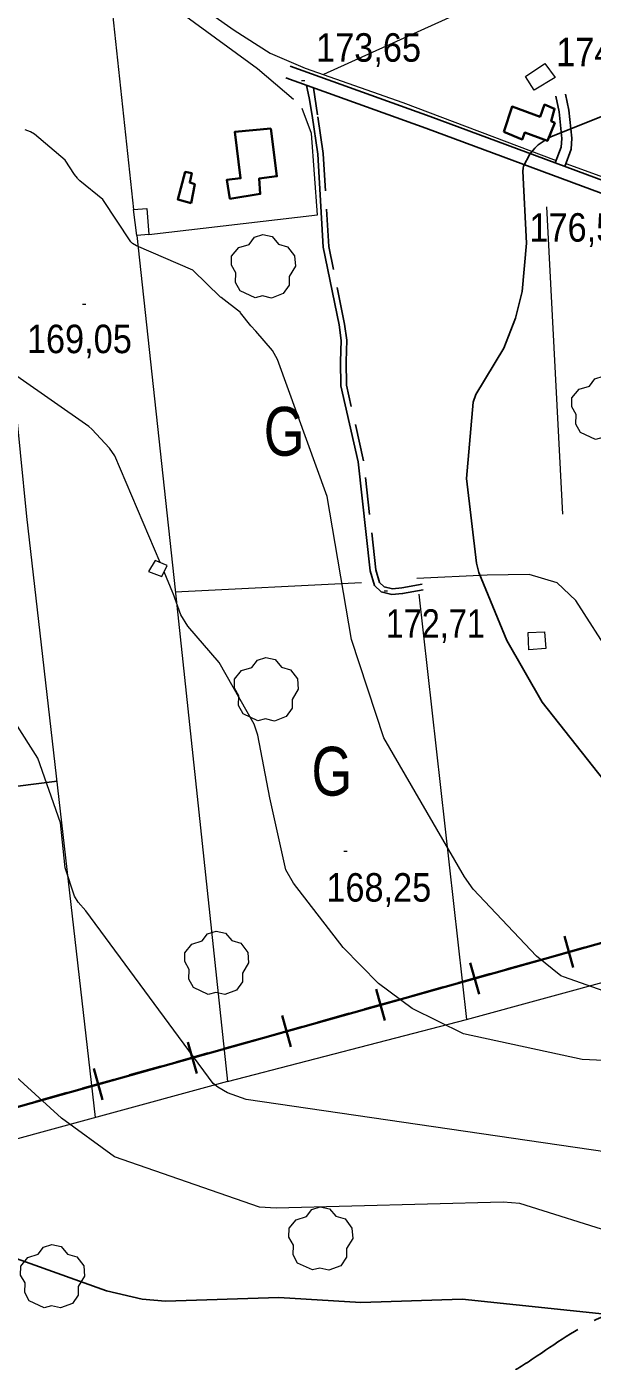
# Model space of a CAD drawing. Extents: x 480269 to 484877, y 4383588 to 4386804.
# Drawn here: x 481607.7 to 481781.2, y 4384664.9 to 4385074.9 of the extents above; entities that cross this region are included whole.
import ezdxf
from ezdxf.enums import TextEntityAlignment as Align

# ---------------------------------------------------------------- set-up
doc = ezdxf.new("R2010")
doc.units = 0
doc.header["$LTSCALE"] = 3.8
doc.linetypes.add('LONG_DASHED', pattern=[7.5, 6, -1.5])
doc.linetypes.add('MEDIUM_DASHED', pattern=[4.5, 3, -1.5])
for name, color, linetype, lineweight in [('25', 7, 'LONG_DASHED', 25), ('29', 7, 'Continuous', 13), ('34', 7, 'Continuous', 35), ('37', 7, 'Continuous', 25), ('38', 7, 'Continuous', 25), ('47', 7, 'Continuous', 35), ('51', 7, 'Continuous', 13), ('7', 7, 'Continuous', 13), ('8', 7, 'Continuous', 25), ('9', 7, 'Continuous', 13)]:
    doc.layers.add(name, color=color, linetype=linetype, lineweight=lineweight)
doc.layers.add('31', color=7, linetype='Continuous')

msp = doc.modelspace()

# ---------------------------------------------------------------- linework, layer by layer
at = {"layer": '25'}
msp.add_lwpolyline([(481616.96, 4384843.18), (481578.36, 4384838.22), (481534.2, 4384832.55)], dxfattribs=at)
at = {"layer": '29'}
for points in [[(481677.72, 4384991.61), (481673.18, 4384993.73), (481671.77, 4384996.27), (481671.87, 4384999.25), (481670.5, 4385001.66), (481670.54, 4385004.41), (481672.7, 4385007.01), (481675.89, 4385008.01), (481677.54, 4385010.2), (481680.11, 4385011.03), (481682.97, 4385010.38), (481684.92, 4385008.11), (481687.73, 4385007.29), (481689.86, 4385004.44), (481690.1, 4385001.31), (481688.22, 4384998.16), (481688.22, 4384995.48), (481686.4, 4384992.87), (481682.78, 4384991.53), (481680.01, 4384992.16)], [(481782.17, 4384948.1), (481777.63, 4384950.22), (481776.22, 4384952.76), (481776.32, 4384955.74), (481774.95, 4384958.15), (481774.99, 4384960.9), (481777.15, 4384963.5), (481780.34, 4384964.5), (481781.99, 4384966.69), (481784.56, 4384967.52), (481787.42, 4384966.87), (481789.37, 4384964.6), (481792.18, 4384963.78), (481794.31, 4384960.93), (481794.55, 4384957.8), (481792.67, 4384954.65), (481792.67, 4384951.97), (481790.85, 4384949.36), (481787.23, 4384948.02), (481784.46, 4384948.65)], [(481678.62, 4384861.69), (481674.08, 4384863.81), (481672.67, 4384866.35), (481672.77, 4384869.33), (481671.4, 4384871.74), (481671.44, 4384874.49), (481673.6, 4384877.09), (481676.79, 4384878.09), (481678.44, 4384880.28), (481681.01, 4384881.11), (481683.87, 4384880.46), (481685.82, 4384878.19), (481688.63, 4384877.37), (481690.76, 4384874.52), (481691, 4384871.39), (481689.12, 4384868.24), (481689.12, 4384865.56), (481687.3, 4384862.95), (481683.68, 4384861.61), (481680.91, 4384862.24)], [(481663.36, 4384777.65), (481658.82, 4384779.77), (481657.41, 4384782.31), (481657.51, 4384785.29), (481656.14, 4384787.7), (481656.18, 4384790.45), (481658.34, 4384793.05), (481661.53, 4384794.05), (481663.18, 4384796.24), (481665.75, 4384797.07), (481668.61, 4384796.42), (481670.56, 4384794.15), (481673.37, 4384793.33), (481675.5, 4384790.48), (481675.74, 4384787.35), (481673.86, 4384784.2), (481673.86, 4384781.52), (481672.04, 4384778.91), (481668.42, 4384777.57), (481665.65, 4384778.2)], [(481695.34, 4384693.01), (481690.8, 4384695.13), (481689.39, 4384697.67), (481689.49, 4384700.65), (481688.12, 4384703.06), (481688.16, 4384705.81), (481690.32, 4384708.41), (481693.51, 4384709.41), (481695.16, 4384711.6), (481697.73, 4384712.43), (481700.59, 4384711.78), (481702.54, 4384709.51), (481705.35, 4384708.69), (481707.48, 4384705.84), (481707.72, 4384702.71), (481705.84, 4384699.56), (481705.84, 4384696.88), (481704.02, 4384694.27), (481700.4, 4384692.93), (481697.63, 4384693.56)], [(481612.99, 4384681.4), (481608.45, 4384683.52), (481607.04, 4384686.06), (481607.14, 4384689.04), (481605.77, 4384691.45), (481605.81, 4384694.2), (481607.97, 4384696.8), (481611.16, 4384697.8), (481612.81, 4384699.99), (481615.38, 4384700.82), (481618.24, 4384700.17), (481620.19, 4384697.9), (481623, 4384697.08), (481625.13, 4384694.23), (481625.37, 4384691.1), (481623.49, 4384687.95), (481623.49, 4384685.27), (481621.67, 4384682.66), (481618.05, 4384681.32), (481615.28, 4384681.95)]]:
    msp.add_lwpolyline(points, close=True, dxfattribs=at)
at = {"layer": '34'}
for p, q in [((481772.65, 4384795.49), (481775.36, 4384785.86)), ((481778.82, 4384792.03), (481769.19, 4384789.32)), ((481743.77, 4384787.37), (481746.48, 4384777.74)), ((481764.38, 4384787.97), (481754.75, 4384785.26)), ((481749.94, 4384783.91), (481740.31, 4384781.2)), ((481714.89, 4384779.25), (481717.6, 4384769.62)), ((481735.5, 4384779.85), (481725.87, 4384777.14)), ((481721.06, 4384775.79), (481711.43, 4384773.08)), ((481686.01, 4384771.12), (481688.72, 4384761.5)), ((481706.62, 4384771.73), (481696.99, 4384769.02)), ((481692.18, 4384767.66), (481682.55, 4384764.96)), ((481657.13, 4384763), (481659.84, 4384753.38)), ((481677.74, 4384763.6), (481668.11, 4384760.9)), ((481663.3, 4384759.54), (481653.67, 4384756.84)), ((481628.25, 4384754.88), (481630.96, 4384745.26)), ((481648.86, 4384755.48), (481639.23, 4384752.78)), ((481634.42, 4384751.42), (481624.79, 4384748.72)), ((481619.98, 4384747.36), (481610.35, 4384744.65))]:
    msp.add_line(p, q, dxfattribs=at)
msp.add_lwpolyline([(482722, 4385145), (482428, 4385006), (482209, 4384913), (481448, 4384699), (481251, 4384637), (481013, 4384577), (480976, 4384524), (480944, 4384410), (480887.47, 4384143.52)], dxfattribs=at)
at = {"layer": '37'}
for points in [[(481688.48, 4385062.75), (481731.45, 4385047.27), (481811.75, 4385017.5), (481890.49, 4384988.72), (481976.99, 4384957.01), (482014.44, 4384943.22), (482020.77, 4384940.55), (482022.89, 4384939.41), (482024.83, 4384937.49), (482026.13, 4384935.48), (482026.91, 4384933.79), (482027.95, 4384931.72), (482028.6, 4384929.95), (482029.12, 4384927.71), (482038.5, 4384849.61)], [(481687.19, 4385059.17), (481730.14, 4385043.69), (481810.44, 4385013.93), (481889.18, 4384985.14), (481975.68, 4384953.43), (482012.99, 4384939.69), (482018.18, 4384937.72), (482020.39, 4384936.36), (482021.47, 4384935.48), (482022.48, 4384933.89), (482023.51, 4384931.99), (482024.83, 4384929.24), (482025.4, 4384926.81), (482034.72, 4384849.16)]]:
    msp.add_lwpolyline(points, dxfattribs=at)
at = {"layer": '38'}
for points in [[(481729.37, 4384901.9), (481723, 4384900.76), (481719.74, 4384900.5), (481716.46, 4384901.27), (481714.4, 4384903.27), (481713.1, 4384907.73), (481709.35, 4384941.26), (481704.04, 4384964.56), (481703.94, 4384972.03), (481704.14, 4384978.51), (481703.52, 4384983.25), (481698.63, 4385007.17), (481696.95, 4385035.74), (481695.22, 4385047.54), (481694.38, 4385052.97), (481693.55, 4385056.78)], [(481769.86, 4385033.03), (481771.72, 4385037.88), (481771.88, 4385040.56), (481771.02, 4385048.71), (481770.01, 4385053.51)]]:
    msp.add_lwpolyline(points, dxfattribs=at)
at = {"layer": '38', "linetype": 'MEDIUM_DASHED'}
for points in [[(481729.06, 4384903.6), (481722.78, 4384902.47), (481719.87, 4384902.24), (481717.32, 4384902.84), (481715.93, 4384904.19), (481714.8, 4384908.07), (481711.05, 4384941.55), (481705.77, 4384964.76), (481705.67, 4384972.01), (481705.87, 4384978.6), (481705.22, 4384983.54), (481700.34, 4385007.39), (481698.66, 4385035.92), (481696.93, 4385047.79), (481695.64, 4385056.12)], [(481772.75, 4385031.96), (481774.77, 4385037.22), (481774.97, 4385040.63), (481774.07, 4385049.19), (481773.02, 4385054.15)]]:
    msp.add_lwpolyline(points, dxfattribs=at)
at = {"layer": '38', "linetype": 'LONG_DASHED'}
msp.add_spline([(481521.41, 4384511.89), (481536.38, 4384525.8), (481549.62, 4384535.04), (481561.93, 4384543.02), (481576.08, 4384552.76), (481592.05, 4384559.89), (481606.4, 4384563.92), (481616.92, 4384565.45), (481628.9, 4384568.67), (481638.46, 4384572.09), (481652.26, 4384579.91), (481664.37, 4384589.24), (481678, 4384597.77), (481682.64, 4384601.91), (481687.21, 4384608.82), (481696.97, 4384617.79), (481710.07, 4384626.85), (481721.95, 4384636.26), (481734.19, 4384647.62), (481744.93, 4384656.56), (481753.4, 4384660.18), (481763.08, 4384665.77), (481783.81, 4384678.41), (481798.11, 4384682.73), (481810.92, 4384683.89), (481823.36, 4384684.59), (481836.86, 4384684.7), (481846.78, 4384682.77), (481856.56, 4384676.35), (481864.94, 4384665.63), (481868.79, 4384658.63), (481875.43, 4384650.52), (481882.64, 4384642.18), (481885.66, 4384630.39), (481885.66, 4384630.29)], degree=3, dxfattribs=at)
at = {"layer": '47', "lineweight": 13}
for points in [[(481763.39, 4385055.41), (481760.77, 4385059.54), (481766.67, 4385063.58), (481769.87, 4385059.25)], [(481645.13, 4385011.06), (481641.43, 4385010.76), (481640.42, 4385018.69), (481644.56, 4385019.03)], [(481649.1, 4384905.98), (481650.72, 4384909.37), (481647.09, 4384910.88), (481645.03, 4384907.54)], [(481766.95, 4384883.83), (481761.79, 4384883.45), (481761.56, 4384888.75), (481766.55, 4384889.01)]]:
    msp.add_lwpolyline(points, close=True, dxfattribs=at)
at = {"layer": '47'}
for points in [[(481754.03, 4385042.57), (481759.73, 4385040.22), (481760.51, 4385042.33), (481767.44, 4385039.78), (481769.71, 4385045.31), (481768.56, 4385045.89), (481769.63, 4385049.67), (481766.57, 4385050.93), (481765.19, 4385047.21), (481756.6, 4385050.31)], [(481682.54, 4385043.62), (481671.51, 4385042.54), (481673.28, 4385028.3), (481669.1, 4385027.83), (481670, 4385022.01), (481679.34, 4385023.51), (481678.95, 4385028.19), (481684.43, 4385028.92)], [(481658.14, 4385020.65), (481654, 4385021.79), (481656.33, 4385030.24), (481658.3, 4385029.87), (481657.69, 4385026.98), (481659.21, 4385026.49)]]:
    msp.add_lwpolyline(points, close=True, dxfattribs=at)
at = {"layer": '51'}
for p, q in [((481775.01, 4385094.76), (481698.75, 4385060.17)), ((481773.08, 4385032.82), (481807.29, 4385020.33)), ((481772.15, 4384925.1), (481767.24, 4385019.54)), ((481653.24, 4384901.32), (481710.42, 4384904.11)), ((481669.29, 4384750.87), (481742.62, 4384769.95))]:
    msp.add_line(p, q, dxfattribs=at)
for points in [[(481497.6, 4385155.25), (481586.75, 4385121.87), (481632.17, 4385096.22), (481640.42, 4385018.69)], [(481638.66, 4385123.08), (481631.48, 4385119.43), (481621.66, 4385111.09), (481621.56, 4385110.13), (481621.84, 4385109.07), (481624.33, 4385106.9), (481671.36, 4385073.76), (481682.36, 4385066.71), (481693.07, 4385062.16), (481723.1, 4385051.59), (481770.15, 4385033.79)], [(481628.79, 4384739.85), (481607.64, 4384924.44), (481588.11, 4385121.11)], [(481689.51, 4385052.5), (481678.44, 4385061.95), (481656.46, 4385077.96), (481632.22, 4385095.79)], [(481645.13, 4385011.06), (481696.87, 4385017.06), (481695.1, 4385042.01), (481692.15, 4385049.73)], [(481641.43, 4385010.76), (481653.18, 4384901.9), (481669.29, 4384750.87), (481548.84, 4384718.07), (481438.36, 4384688.59), (481367.94, 4384669.86), (481313.99, 4384654.58), (481299.42, 4384645.41)], [(481974.06, 4384832.38), (481836.63, 4384795.61), (481787.33, 4384881.2), (481776.2, 4384898.59), (481770.41, 4384904.08), (481761.89, 4384906.59), (481748.99, 4384906.41), (481727.4, 4384905.41)], [(481727.97, 4384900.52), (481742.62, 4384769.95), (481836.63, 4384795.61)]]:
    msp.add_lwpolyline(points, dxfattribs=at)
at = {"layer": '7'}
for p, q in [((481691.96, 4385058.3), (481692.96, 4385058.3)), ((481624.78, 4384989.63), (481625.78, 4384989.63)), ((481717.33, 4384901.55), (481718.33, 4384901.55)), ((481704.98, 4384821.68), (481705.98, 4384821.68))]:
    msp.add_line(p, q, dxfattribs=at)
at = {"layer": '8'}
for points in [[(481818.95, 4385075.2), (481817.71, 4385074.76), (481816.13, 4385073.9), (481814.18, 4385072.39), (481807.77, 4385065.18), (481794.38, 4385053.38), (481787.17, 4385048.55), (481768.52, 4385041.05), (481767.79, 4385040.64)], [(481766.78, 4385040.02), (481764.64, 4385038.54), (481763.59, 4385037.58), (481762.08, 4385035.71), (481760.15, 4385031.98), (481760.01, 4385031.46), (481759.87, 4385030.51), (481761.02, 4385008.36), (481759.73, 4384993.58), (481757.64, 4384985.34), (481754.07, 4384976.09), (481745.45, 4384961.85), (481744.67, 4384959.54), (481742.64, 4384936.14), (481745.68, 4384910.11)], [(481745.68, 4384910.11), (481746.36, 4384907.18), (481755.01, 4384886.34), (481765.87, 4384867.37), (481795.19, 4384830.22), (481817.98, 4384813), (481830.95, 4384801.41), (481832.02, 4384800.68), (481838.79, 4384796.99), (481870.93, 4384788.93)], [(481600.38, 4384697.92), (481632.09, 4384686.63)], [(481632.09, 4384686.63), (481643.09, 4384683.98), (481650.27, 4384683.43), (481685.06, 4384684.49), (481710.2, 4384683.04), (481741.26, 4384683.98), (481824.11, 4384675.34), (481825.19, 4384674.91), (481832.69, 4384670.94), (481835.6, 4384668.78), (481863.82, 4384635.27), (481869.56, 4384631.49), (481873.5, 4384627.3)]]:
    msp.add_lwpolyline(points, dxfattribs=at)
at = {"layer": '9'}
for points in [[(481788.03, 4384777.47), (481772.66, 4384782.9), (481771.62, 4384783.39), (481764.13, 4384789.33), (481744.66, 4384809.92), (481741.98, 4384813.75), (481717.27, 4384856.4), (481707.33, 4384886.68), (481699.84, 4384930.53), (481684.58, 4384972.69), (481683.13, 4384975.42), (481677.95, 4384981.32), (481676.44, 4384982.94), (481673.28, 4384986.99), (481673.26, 4384986.98), (481673.25, 4384986.99), (481673.23, 4384987.03), (481667.37, 4384991.64), (481667.14, 4384991.76), (481658.64, 4385000.13), (481641.37, 4385007.51), (481640.13, 4385008.29), (481639.56, 4385008.77), (481630.97, 4385021.81), (481623.96, 4385027.54), (481623.36, 4385028.14), (481623.24, 4385028.37), (481622.33, 4385029.45), (481622.34, 4385029.47), (481622.34, 4385029.48), (481619.48, 4385033.85), (481619.45, 4385033.88), (481619.44, 4385033.89), (481619.43, 4385033.9), (481610.05, 4385041.86), (481608.85, 4385042.55), (481607.14, 4385043.21)], [(481648.62, 4384910.25), (481634.71, 4384943.08), (481633.04, 4384945.45), (481627.68, 4384951.26), (481626.75, 4384952.05), (481583.48, 4384982.25)], [(482015.4, 4384662.18), (481962.36, 4384682.52), (481957.47, 4384685.23), (481866.84, 4384737.74), (481856.89, 4384744.2), (481827.08, 4384752.9), (481802.44, 4384756.48), (481778.15, 4384757.62), (481741.65, 4384765.51), (481725.99, 4384773.3), (481715.57, 4384781.03), (481704.76, 4384792.05), (481689.5, 4384811.78), (481687.15, 4384815.94), (481682.22, 4384838.04), (481678.61, 4384857.22), (481677.48, 4384860.67), (481666.7, 4384879.61), (481657.14, 4384890.75), (481654.97, 4384894.19), (481652.59, 4384900.76), (481652.53, 4384901.02), (481649.8, 4384907.45)], [(481622.32, 4384807.77), (481619.48, 4384816.46), (481617.98, 4384830.29), (481611.03, 4384850.19), (481579.06, 4384900.48)], [(481958.99, 4384648.31), (481923.65, 4384666.53), (481922.24, 4384667.06), (481921.59, 4384667.39), (481890.02, 4384692.58), (481866.48, 4384704.02), (481849.5, 4384715.33), (481838.86, 4384720.49), (481824.2, 4384724.61), (481809.59, 4384726.14), (481804.7, 4384726.4), (481674.95, 4384745.34), (481669.27, 4384747.43), (481666.27, 4384749.12), (481664.85, 4384750.25), (481625.81, 4384803.27), (481623.47, 4384805.95), (481622.32, 4384807.77)], [(481847.73, 4384690.48), (481843.5, 4384692.83), (481811.71, 4384701.04), (481789.61, 4384703.75), (481758.94, 4384713.41), (481753.9, 4384713.87), (481684.16, 4384711.98), (481679.06, 4384712.31), (481634.61, 4384727.73), (481618.32, 4384739.6), (481598.54, 4384757.54)]]:
    msp.add_lwpolyline(points, dxfattribs=at)

# ---------------------------------------------------------------- texts
at = {"layer": '31', "width": 0.8}
for p in [(481686.65, 4384943.09), (481701.3, 4384838.69)]:
    msp.add_text('G', height=15, dxfattribs=at).set_placement(p, align=Align.CENTER)
at = {"layer": '7'}
for s, width, p in [('173,65', 0.9, (481696.46, 4385064.11)), ('174,62', 0.9, (481770.15, 4385062.72)), ('176,56', 0.9, (481761.93, 4385008.84)), ('169,05', 0.9, (481607.71, 4384974.59)), ('172,71', 0.85, (481717.83, 4384887.18)), ('168,25', 0.9, (481699.59, 4384806.13))]:
    msp.add_text(s, height=8.75, dxfattribs=dict(at, width=width)).set_placement(p)

doc.saveas('drawing.dxf')
